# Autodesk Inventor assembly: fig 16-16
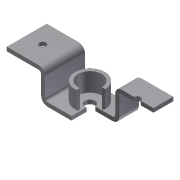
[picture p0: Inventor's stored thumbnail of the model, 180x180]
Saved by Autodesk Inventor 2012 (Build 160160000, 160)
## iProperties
Created: 2005-03
Part Number: fig 16-16
Document SubType Name: Weldment
Designer: CADCIM
Manufacturer: Standard
Standards Organization: Custom
Author: CADCIM
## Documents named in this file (3)
- C:\Users\CadCim\Documents\SAILESH\inventor-2011-fact-prt\c16-inv-2011-prt\c16_inv_2012_prt\fig 16-16\fig 16-16.iam
- C:\Users\CadCim\Documents\SAILESH\inventor-2011-fact-prt\c16-inv-2011-prt\fig-16-16\Bracket.ipt
- C:\Users\CadCim\Documents\SAILESH\inventor-2011-fact-prt\c16-inv-2011-prt\fig-16-16\cylinder.ipt
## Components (2 placed, 2 different names)
1. Bracket:1 — Insert:1
2. cylinder:1 — Insert:1
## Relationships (1: Insert 1)
- Insert:1: Bracket:1 ↔ cylinder:1
